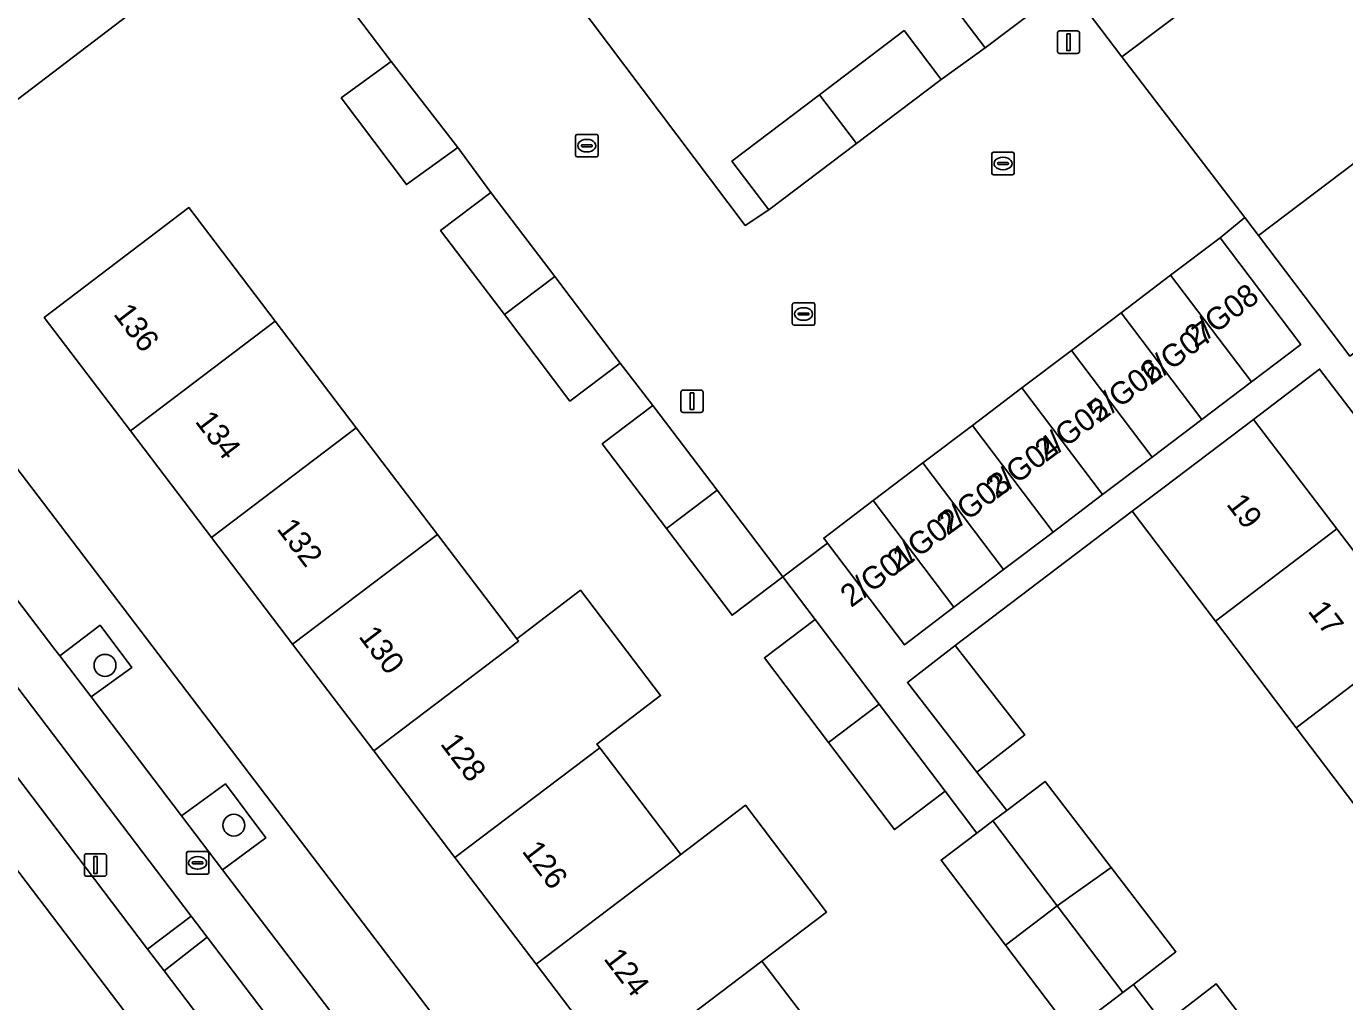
# Model space of a CAD drawing. Extents: x 160030 to 160839, y 385325 to 386450.
# Drawn here: x 160239.1 to 160297.9, y 385818.7 to 385862.2 of the extents above; entities that cross this region are included whole.
import ezdxf

# ---------------------------------------------------------------- set-up
doc = ezdxf.new("R2010")
doc.units = 0
for name, color, linetype in [('IMGEO_Berm_groen', 7, 'Continuous'), ('IMGEO_Boom', 7, 'Continuous'), ('IMGEO_Erf', 7, 'Continuous'), ('IMGEO_Fietspad_gesloten', 7, 'Continuous'), ('IMGEO_Groenvoorziening', 7, 'Continuous'), ('IMGEO_Kolk', 7, 'Continuous'), ('IMGEO_Lichtmast', 7, 'Continuous'), ('IMGEO_Muur', 7, 'Continuous'), ('IMGEO_Pand', 7, 'Continuous'), ('IMGEO_Pand_nummerreeks', 7, 'Continuous'), ('IMGEO_Parkeervlak_open', 7, 'Continuous'), ('IMGEO_Rijbaan_lokaal_gesloten', 7, 'Continuous'), ('IMGEO_Rijbaan_lokaal_open', 7, 'Continuous'), ('IMGEO_Rioolput', 7, 'Continuous'), ('IMGEO_Voetpad_open', 7, 'Continuous')]:
    doc.layers.add(name, color=color, linetype=linetype)

msp = doc.modelspace()

# ---------------------------------------------------------------- linework, layer by layer
at = {"layer": 'IMGEO_Berm_groen'}
msp.add_lwpolyline([(160233.389, 385835.707), (160244.52, 385821.036), (160246.466, 385822.505), (160230.756, 385843.173)], dxfattribs=at)
msp.add_lwpolyline([(160247.179, 385821.566), (160245.256, 385820.064), (160263.382, 385796.182), (160265.333, 385797.683)], close=True, dxfattribs=at)
at = {"layer": 'IMGEO_Boom'}
for centre in [(160242.62, 385833.683), (160248.364, 385826.556)]:
    msp.add_circle(centre, 0.489, dxfattribs=at)
at = {"layer": 'IMGEO_Erf'}
for points in [[(160301.566, 385871.532), (160297.525, 385868.388), (160293.797, 385865.487), (160292.351, 385867.345), (160290.31, 385865.8), (160291.853, 385863.763), (160287.96, 385860.815), (160293.444, 385853.652), (160294.063, 385852.843), (160298.997, 385856.578)], [(160282.773, 385821.214), (160279.908, 385824.999), (160281.504, 385826.208), (160280.082, 385828.07), (160277.823, 385826.36), (160274.88, 385830.247), (160272.027, 385834.013), (160274.287, 385835.724), (160272.844, 385837.629), (160270.584, 385835.918), (160267.655, 385839.784), (160264.796, 385843.558), (160267.057, 385845.271), (160265.599, 385847.156), (160263.356, 385845.459), (160260.431, 385849.321), (160257.588, 385853.075), (160259.832, 385854.773), (160258.354, 385856.767), (160256.06, 385855.12), (160253.159, 385858.988), (160255.38, 385860.608), (160250.09, 385867.593), (160231.698, 385853.575)], [(160263.526, 385863.454), (160271.171, 385853.296), (160272.221, 385853.995), (160270.574, 385856.169), (160274.482, 385859.128), (160278.257, 385861.986), (160279.903, 385859.811), (160281.865, 385861.216), (160280.157, 385863.471)], [(160265.465, 385815.599), (160261.846, 385820.356), (160258.227, 385825.114), (160254.608, 385829.871), (160250.989, 385834.629), (160247.371, 385839.385), (160243.752, 385844.143), (160239.913, 385849.19), (160246.36, 385854.094), (160250.206, 385849.038), (160253.824, 385844.281), (160257.443, 385839.524), (160260.981, 385834.873), (160263.823, 385837.034), (160267.396, 385832.337), (160264.554, 385830.176), (160264.68, 385830.01), (160268.299, 385825.253), (160271.19, 385827.447), (160274.802, 385822.686), (160271.917, 385820.496), (160275.536, 385815.739)], [(160231.475, 385851.922), (160294.583, 385769.052)], [(160302.585, 385841.09), (160301.695, 385840.441), (160299.39, 385843.472), (160296.787, 385846.896), (160293.838, 385844.652), (160297.555, 385839.767), (160301.163, 385835.026), (160304.771, 385830.284), (160308.379, 385825.543), (160311.987, 385820.801), (160315.595, 385816.06), (160319.203, 385811.318), (160322.811, 385806.577), (160326.419, 385801.836), (160330.134, 385796.954), (160325.136, 385793.154)], [(160306.531, 385816.65), (160302.935, 385821.4), (160299.338, 385826.151), (160295.742, 385830.901), (160292.145, 385835.651), (160288.43, 385840.558), (160280.539, 385834.575), (160283.637, 385830.585), (160281.5, 385828.925), (160282.831, 385827.212), (160284.541, 385828.507), (160287.487, 385824.671), (160290.373, 385820.913), (160288.481, 385819.459), (160289.842, 385817.685), (160292.178, 385819.479), (160295.203, 385815.538)], [(160285.703, 385817.345), (160282.773, 385821.214)]]:
    msp.add_lwpolyline(points, dxfattribs=at)
at = {"layer": 'IMGEO_Fietspad_gesloten'}
for points in [[(160255.179, 385814.968), (160253.742, 385816.855), (160253.509, 385817.161), (160247.864, 385824.573), (160246.034, 385826.977), (160241.998, 385832.275), (160240.606, 385834.102), (160240.383, 385834.395), (160233.264, 385843.741), (160231.245, 385846.393), (160228.63, 385849.846), (160226.256, 385852.983)], [(160225.501, 385850.09), (160229.487, 385844.842), (160230.756, 385843.173), (160246.466, 385822.505), (160247.179, 385821.566), (160265.333, 385797.683), (160266.08, 385796.701), (160277.414, 385781.789), (160278.156, 385780.813), (160284.988, 385771.823), (160286.475, 385769.866), (160289.911, 385765.345)]]:
    msp.add_lwpolyline(points, dxfattribs=at)
at = {"layer": 'IMGEO_Groenvoorziening'}
for points in [[(160242.401, 385835.469), (160240.606, 385834.102), (160241.998, 385832.275), (160243.811, 385833.588)], [(160247.987, 385828.396), (160246.034, 385826.977), (160247.864, 385824.573), (160249.79, 385825.991)]]:
    msp.add_lwpolyline(points, close=True, dxfattribs=at)
at = {"layer": 'IMGEO_Kolk'}
for p, q in [((160263.605, 385856.428), (160263.605, 385857.28)), ((160263.68, 385857.354), (160264.532, 385857.354)), ((160263.864, 385856.848), (160263.864, 385856.86)), ((160263.907, 385856.897), (160264.305, 385856.897)), ((160264.093, 385857.134), (160264.118, 385857.134)), ((160264.348, 385856.86), (160264.348, 385856.848)), ((160264.606, 385857.28), (160264.606, 385856.428)), ((160264.532, 385856.354), (160263.68, 385856.354)), ((160264.302, 385856.811), (160263.904, 385856.811)), ((160264.116, 385856.574), (160264.091, 385856.574)), ((160282.166, 385855.635), (160282.166, 385856.487)), ((160282.241, 385856.561), (160283.093, 385856.561)), ((160282.654, 385856.341), (160282.679, 385856.341)), ((160283.167, 385856.487), (160283.167, 385855.635)), ((160282.425, 385856.055), (160282.425, 385856.067)), ((160282.863, 385856.018), (160282.465, 385856.018)), ((160282.468, 385856.104), (160282.866, 385856.104)), ((160282.677, 385855.781), (160282.652, 385855.781)), ((160282.909, 385856.067), (160282.909, 385856.055)), ((160283.093, 385855.561), (160282.241, 385855.561)), ((160273.346, 385849.851), (160274.198, 385849.851)), ((160273.271, 385848.925), (160273.271, 385849.777)), ((160273.53, 385849.345), (160273.53, 385849.357)), ((160273.968, 385849.308), (160273.57, 385849.308)), ((160273.573, 385849.394), (160273.971, 385849.394)), ((160273.759, 385849.631), (160273.784, 385849.631)), ((160274.014, 385849.357), (160274.014, 385849.345)), ((160274.272, 385849.777), (160274.272, 385848.925)), ((160274.198, 385848.851), (160273.346, 385848.851)), ((160273.782, 385849.071), (160273.757, 385849.071))]:
    msp.add_line(p, q, dxfattribs=at)
for points in [[(160263.605, 385856.428), (160263.605, 385857.28)], [(160263.68, 385857.354), (160264.532, 385857.354)], [(160264.606, 385857.28), (160264.606, 385856.428)], [(160264.532, 385856.354), (160263.68, 385856.354)], [(160282.166, 385855.635), (160282.166, 385856.487)], [(160282.241, 385856.561), (160283.093, 385856.561)], [(160283.167, 385856.487), (160283.167, 385855.635)], [(160283.093, 385855.561), (160282.241, 385855.561)], [(160273.346, 385849.851), (160274.198, 385849.851)], [(160273.271, 385848.925), (160273.271, 385849.777)], [(160274.272, 385849.777), (160274.272, 385848.925)], [(160274.198, 385848.851), (160273.346, 385848.851)]]:
    msp.add_lwpolyline(points, dxfattribs=at)
for centre, radius, start, end in [((160263.682, 385857.278), 0.0765, 91.55205, 178.44795), ((160263.682, 385857.278), 0.0765, 91.55205, 178.44795), ((160263.904, 385856.857), 0.0403, 85.87752, 175.75265), ((160263.901, 385856.847), 0.0366, 178.93798, 274.71019), ((160264.305, 385856.854), 0.043, 264.86636, 352.45326), ((160264.309, 385856.859), 0.0386, 1.73085, 96.63898), ((160264.53, 385857.278), 0.0765, 1.55205, 88.44795), ((160264.53, 385857.278), 0.0765, 1.55205, 88.44795), ((160263.682, 385856.43), 0.0765, 181.55205, 268.44795), ((160263.682, 385856.43), 0.0765, 181.55205, 268.44795), ((160264.53, 385856.43), 0.0765, 271.55205, 358.44795), ((160264.53, 385856.43), 0.0765, 271.55205, 358.44795), ((160282.243, 385856.485), 0.0765, 91.55205, 178.44795), ((160282.243, 385856.485), 0.0765, 91.55205, 178.44795), ((160283.091, 385856.485), 0.0765, 1.55205, 88.44795), ((160283.091, 385856.485), 0.0765, 1.55205, 88.44795), ((160282.465, 385856.064), 0.0403, 85.87752, 175.75265), ((160282.462, 385856.054), 0.0366, 178.93798, 274.71019), ((160282.866, 385856.061), 0.043, 264.86636, 352.45326), ((160282.87, 385856.066), 0.0386, 1.73085, 96.63898), ((160282.243, 385855.637), 0.0765, 181.55205, 268.44795), ((160282.243, 385855.637), 0.0765, 181.55205, 268.44795), ((160283.091, 385855.637), 0.0765, 271.55205, 358.44795), ((160283.091, 385855.637), 0.0765, 271.55205, 358.44795), ((160273.348, 385849.775), 0.0765, 91.55205, 178.44795), ((160273.348, 385849.775), 0.0765, 91.55205, 178.44795), ((160274.196, 385849.775), 0.0765, 1.55205, 88.44795), ((160274.196, 385849.775), 0.0765, 1.55205, 88.44795), ((160273.57, 385849.354), 0.0403, 85.87752, 175.75265), ((160273.567, 385849.344), 0.0366, 178.93798, 274.71019), ((160273.971, 385849.351), 0.043, 264.86636, 352.45326), ((160273.975, 385849.356), 0.0386, 1.73085, 96.63898), ((160273.348, 385848.927), 0.0765, 181.55205, 268.44795), ((160273.348, 385848.927), 0.0765, 181.55205, 268.44795), ((160274.196, 385848.927), 0.0765, 271.55205, 358.44795), ((160274.196, 385848.927), 0.0765, 271.55205, 358.44795)]:
    msp.add_arc(centre, radius, start, end, dxfattribs=at)
for centre, major_axis, ratio, start_param, end_param in [((160264.092, 385856.854), (-0.387, 0.002), 0.722429, 4.712389, 7.853982), ((160264.117, 385856.854), (-0.39, 0.002), 0.717154, 1.570796, 4.712389), ((160282.653, 385856.061), (-0.387, 0.002), 0.722429, 4.712389, 7.853982), ((160282.678, 385856.061), (-0.39, 0.002), 0.717154, 1.570796, 4.712389), ((160273.758, 385849.351), (-0.387, 0.002), 0.722429, 4.712389, 7.853982), ((160273.783, 385849.351), (-0.39, 0.002), 0.717154, 1.570796, 4.712389)]:
    msp.add_ellipse(centre, major_axis=major_axis, ratio=ratio, start_param=start_param, end_param=end_param, dxfattribs=at)
at = {"layer": 'IMGEO_Lichtmast'}
for p, q in [((160285.09, 385861.069), (160285.09, 385861.869)), ((160285.09, 385861.869), (160285.09, 385861.069)), ((160285.19, 385861.969), (160285.98, 385861.969)), ((160285.98, 385861.969), (160285.19, 385861.969)), ((160286.08, 385861.869), (160286.08, 385861.069)), ((160286.08, 385861.069), (160286.08, 385861.869)), ((160285.98, 385860.969), (160285.19, 385860.969)), ((160285.19, 385860.969), (160285.98, 385860.969)), ((160268.302, 385845.06), (160268.302, 385845.86)), ((160268.302, 385845.86), (160268.302, 385845.06)), ((160268.402, 385845.96), (160269.192, 385845.96)), ((160269.192, 385845.96), (160268.402, 385845.96)), ((160269.292, 385845.86), (160269.292, 385845.06)), ((160269.292, 385845.06), (160269.292, 385845.86)), ((160269.192, 385844.96), (160268.402, 385844.96)), ((160268.402, 385844.96), (160269.192, 385844.96)), ((160241.699, 385824.381), (160241.699, 385825.181)), ((160241.699, 385825.181), (160241.699, 385824.381)), ((160241.799, 385825.281), (160242.589, 385825.281)), ((160242.589, 385825.281), (160241.799, 385825.281)), ((160242.689, 385825.181), (160242.689, 385824.381)), ((160242.689, 385824.381), (160242.689, 385825.181)), ((160242.589, 385824.281), (160241.799, 385824.281)), ((160241.799, 385824.281), (160242.589, 385824.281))]:
    msp.add_line(p, q, dxfattribs=at)
for points in [[(160285.51, 385861.844), (160285.66, 385861.844), (160285.66, 385861.094), (160285.51, 385861.094), (160285.51, 385861.844)], [(160268.722, 385845.835), (160268.872, 385845.835), (160268.872, 385845.085), (160268.722, 385845.085), (160268.722, 385845.835)], [(160242.119, 385825.156), (160242.269, 385825.156), (160242.269, 385824.406), (160242.119, 385824.406), (160242.119, 385825.156)]]:
    msp.add_lwpolyline(points, dxfattribs=at)
for centre, start, end in [((160285.19, 385861.869), 90, 180), ((160285.19, 385861.869), 90, 180), ((160285.98, 385861.869), 0, 90), ((160285.98, 385861.869), 360, 90), ((160285.19, 385861.069), 180, 270), ((160285.19, 385861.069), 180, 270), ((160285.98, 385861.069), 270, 0), ((160285.98, 385861.069), 270, 0), ((160268.402, 385845.86), 90, 180), ((160268.402, 385845.86), 90, 180), ((160269.192, 385845.86), 0, 90), ((160269.192, 385845.86), 360, 90), ((160268.402, 385845.06), 180, 270), ((160268.402, 385845.06), 180, 270), ((160269.192, 385845.06), 270, 0), ((160269.192, 385845.06), 270, 0), ((160241.799, 385825.181), 90, 180), ((160241.799, 385825.181), 90, 180), ((160242.589, 385825.181), 0, 90), ((160242.589, 385825.181), 360, 90), ((160241.799, 385824.381), 180, 270), ((160241.799, 385824.381), 180, 270), ((160242.589, 385824.381), 270, 0), ((160242.589, 385824.381), 270, 0)]:
    msp.add_arc(centre, 0.1, start, end, dxfattribs=at)
at = {"layer": 'IMGEO_Muur'}
for points in [[(160263.526, 385863.454), (160271.171, 385853.296)], [(160287.96, 385860.815), (160293.444, 385853.652)], [(160293.444, 385853.652), (160294.063, 385852.843)]]:
    msp.add_lwpolyline(points, dxfattribs=at)
at = {"layer": 'IMGEO_Pand'}
for points in [[(160285.544, 385864.002), (160285.742, 385864.152), (160284.035, 385866.407), (160280.157, 385863.471), (160281.865, 385861.216)], [(160291.853, 385863.763), (160290.31, 385865.8), (160286.417, 385862.852), (160287.96, 385860.815)], [(160279.903, 385859.811), (160278.257, 385861.986), (160274.482, 385859.128), (160276.129, 385856.954)], [(160255.38, 385860.608), (160253.159, 385858.988), (160256.06, 385855.12), (160258.354, 385856.767)], [(160276.129, 385856.954), (160274.482, 385859.128), (160270.574, 385856.169), (160272.221, 385853.995)], [(160294.063, 385852.843), (160298.129, 385847.473), (160303.062, 385851.208), (160298.997, 385856.578)], [(160259.832, 385854.773), (160257.588, 385853.075), (160260.431, 385849.321), (160262.673, 385851.02)], [(160250.206, 385849.038), (160246.36, 385854.094), (160239.913, 385849.19), (160243.752, 385844.143)], [(160295.951, 385847.992), (160292.35, 385852.748), (160290.14, 385851.075), (160293.741, 385846.319)], [(160262.673, 385851.02), (160260.431, 385849.321), (160263.356, 385845.459), (160265.599, 385847.156)], [(160293.741, 385846.319), (160290.14, 385851.075), (160287.93, 385849.401), (160291.531, 385844.645)], [(160291.531, 385844.645), (160287.93, 385849.401), (160285.72, 385847.728), (160289.321, 385842.972)], [(160243.752, 385844.143), (160247.371, 385839.385), (160253.824, 385844.281), (160250.206, 385849.038)], [(160289.321, 385842.972), (160285.72, 385847.728), (160283.51, 385846.055), (160287.11, 385841.299)], [(160287.11, 385841.299), (160283.51, 385846.055), (160281.299, 385844.381), (160284.9, 385839.625)], [(160267.057, 385845.271), (160264.796, 385843.558), (160267.655, 385839.784), (160269.916, 385841.496)], [(160297.555, 385839.767), (160293.838, 385844.652), (160289.852, 385841.635), (160288.43, 385840.558), (160292.145, 385835.651)], [(160257.443, 385839.524), (160253.824, 385844.281), (160247.371, 385839.385), (160250.989, 385834.629)], [(160284.9, 385839.625), (160281.299, 385844.381), (160279.089, 385842.708), (160282.69, 385837.952)], [(160282.69, 385837.952), (160279.089, 385842.708), (160276.879, 385841.034), (160280.48, 385836.278)], [(160269.916, 385841.496), (160267.655, 385839.784), (160270.584, 385835.918), (160272.844, 385837.629)], [(160278.27, 385834.605), (160280.48, 385836.278), (160276.879, 385841.034), (160274.669, 385839.361), (160274.843, 385839.132)], [(160261.061, 385834.768), (160260.981, 385834.873), (160257.443, 385839.524), (160250.989, 385834.629), (160254.608, 385829.871)], [(160292.145, 385835.651), (160295.742, 385830.901), (160301.163, 385835.026), (160297.555, 385839.767)], [(160264.68, 385830.01), (160264.554, 385830.176), (160267.396, 385832.337), (160263.823, 385837.034), (160260.981, 385834.873), (160261.061, 385834.768), (160254.608, 385829.871), (160258.227, 385825.114)], [(160274.287, 385835.724), (160272.027, 385834.013), (160274.88, 385830.247), (160277.139, 385831.957)], [(160278.402, 385832.916), (160281.5, 385828.925), (160283.637, 385830.585), (160280.539, 385834.575)], [(160304.771, 385830.284), (160301.163, 385835.026), (160295.742, 385830.901), (160299.338, 385826.151)], [(160277.139, 385831.957), (160274.88, 385830.247), (160277.823, 385826.36), (160280.082, 385828.07)], [(160268.299, 385825.253), (160264.68, 385830.01), (160258.227, 385825.114), (160261.846, 385820.356)], [(160282.831, 385827.212), (160282.218, 385826.748), (160285.083, 385822.963), (160287.487, 385824.671), (160284.541, 385828.507)], [(160271.917, 385820.496), (160274.802, 385822.686), (160271.19, 385827.447), (160268.299, 385825.253), (160261.846, 385820.356), (160265.465, 385815.599)], [(160282.218, 385826.748), (160281.504, 385826.208), (160279.908, 385824.999), (160282.773, 385821.214), (160285.083, 385822.963)], [(160287.487, 385824.671), (160285.083, 385822.963), (160288.011, 385819.098), (160288.481, 385819.459), (160290.373, 385820.913)], [(160285.083, 385822.963), (160282.773, 385821.214), (160285.703, 385817.345), (160287.329, 385818.58), (160288.011, 385819.098)], [(160275.536, 385815.739), (160271.917, 385820.496), (160265.465, 385815.599), (160269.083, 385810.842)], [(160295.203, 385815.538), (160292.178, 385819.479), (160289.842, 385817.685), (160292.859, 385813.755)]]:
    msp.add_lwpolyline(points, close=True, dxfattribs=at)
at = {"layer": 'IMGEO_Parkeervlak_open'}
for points in [[(160228.526, 385837.944), (160279.223, 385771.231)], [(160278.331, 385776.525), (160276.196, 385779.33), (160275.455, 385780.303), (160264.086, 385795.256), (160263.382, 385796.182), (160245.256, 385820.064), (160244.52, 385821.036), (160233.389, 385835.707)]]:
    msp.add_lwpolyline(points, dxfattribs=at)
at = {"layer": 'IMGEO_Rijbaan_lokaal_gesloten'}
msp.add_lwpolyline([(160278.119, 385766.625), (160281.119, 385768.748), (160279.223, 385771.231), (160228.526, 385837.944), (160226.826, 385840.11), (160225.579, 385841.807), (160224.418, 385843.405), (160212.483, 385859.092), (160208.116, 385864.799), (160181.103, 385900.416), (160180.357, 385901.406), (160179.584, 385902.465), (160175.453, 385899.617), (160202.503, 385863.561), (160272.577, 385773.993)], close=True, dxfattribs=at)
at = {"layer": 'IMGEO_Rijbaan_lokaal_open'}
for points in [[(160250.09, 385867.593), (160255.38, 385860.608), (160258.354, 385856.767), (160259.832, 385854.773), (160262.673, 385851.02), (160265.599, 385847.156), (160267.057, 385845.271), (160269.916, 385841.496), (160272.844, 385837.629), (160274.843, 385839.132), (160274.669, 385839.361), (160276.879, 385841.034), (160279.089, 385842.708), (160281.299, 385844.381), (160283.51, 385846.055), (160285.72, 385847.728), (160287.93, 385849.401), (160290.14, 385851.075), (160292.35, 385852.748), (160293.444, 385853.652), (160287.96, 385860.815), (160286.417, 385862.852)], [(160285.544, 385864.002), (160281.865, 385861.216), (160279.903, 385859.811), (160276.129, 385856.954), (160272.221, 385853.995), (160271.171, 385853.296), (160263.526, 385863.454)]]:
    msp.add_lwpolyline(points, dxfattribs=at)
at = {"layer": 'IMGEO_Rioolput'}
for p, q in [((160246.251, 385824.452), (160246.251, 385825.304)), ((160246.326, 385825.378), (160247.178, 385825.378)), ((160246.739, 385825.158), (160246.764, 385825.158)), ((160247.252, 385825.304), (160247.252, 385824.452)), ((160246.51, 385824.872), (160246.51, 385824.884)), ((160246.948, 385824.835), (160246.55, 385824.835)), ((160246.553, 385824.921), (160246.951, 385824.921)), ((160246.762, 385824.598), (160246.737, 385824.598)), ((160246.994, 385824.884), (160246.994, 385824.872)), ((160247.178, 385824.378), (160246.326, 385824.378))]:
    msp.add_line(p, q, dxfattribs=at)
for points in [[(160246.251, 385824.452), (160246.251, 385825.304)], [(160246.326, 385825.378), (160247.178, 385825.378)], [(160247.252, 385825.304), (160247.252, 385824.452)], [(160247.178, 385824.378), (160246.326, 385824.378)]]:
    msp.add_lwpolyline(points, dxfattribs=at)
for centre, radius, start, end in [((160246.328, 385825.302), 0.0765, 91.55205, 178.44795), ((160246.328, 385825.302), 0.0765, 91.55205, 178.44795), ((160247.176, 385825.302), 0.0765, 1.55205, 88.44795), ((160247.176, 385825.302), 0.0765, 1.55205, 88.44795), ((160246.55, 385824.881), 0.0403, 85.87752, 175.75265), ((160246.547, 385824.871), 0.0366, 178.93798, 274.71019), ((160246.951, 385824.878), 0.043, 264.86636, 352.45326), ((160246.955, 385824.883), 0.0386, 1.73085, 96.63898), ((160246.328, 385824.454), 0.0765, 181.55205, 268.44795), ((160246.328, 385824.454), 0.0765, 181.55205, 268.44795), ((160247.176, 385824.454), 0.0765, 271.55205, 358.44795), ((160247.176, 385824.454), 0.0765, 271.55205, 358.44795)]:
    msp.add_arc(centre, radius, start, end, dxfattribs=at)
for centre, major_axis, ratio, start_param, end_param in [((160246.738, 385824.878), (-0.387, 0.002), 0.722429, 4.712389, 7.853982), ((160246.763, 385824.878), (-0.39, 0.002), 0.717154, 1.570796, 4.712389)]:
    msp.add_ellipse(centre, major_axis=major_axis, ratio=ratio, start_param=start_param, end_param=end_param, dxfattribs=at)
at = {"layer": 'IMGEO_Voetpad_open'}
for points in [[(160250.09, 385867.593), (160251.271, 385868.357), (160248.486, 385870.73), (160229.444, 385856.309), (160231.698, 385853.575)], [(160244.52, 385821.036), (160245.256, 385820.064), (160247.179, 385821.566), (160246.466, 385822.505)]]:
    msp.add_lwpolyline(points, close=True, dxfattribs=at)
for points in [[(160298.129, 385847.473), (160294.063, 385852.843), (160293.444, 385853.652), (160292.35, 385852.748), (160295.951, 385847.992), (160293.741, 385846.319), (160291.531, 385844.645), (160289.321, 385842.972), (160287.11, 385841.299), (160284.9, 385839.625), (160282.69, 385837.952), (160280.48, 385836.278), (160278.27, 385834.605), (160274.843, 385839.132), (160272.844, 385837.629), (160274.287, 385835.724), (160277.139, 385831.957), (160280.082, 385828.07), (160281.504, 385826.208), (160282.218, 385826.748), (160282.831, 385827.212), (160281.5, 385828.925), (160278.402, 385832.916), (160280.539, 385834.575), (160288.43, 385840.558), (160289.852, 385841.635), (160293.838, 385844.652), (160296.787, 385846.896), (160299.39, 385843.472)], [(160296.233, 385766.885), (160294.598, 385769.03), (160294.583, 385769.052), (160231.475, 385851.922)], [(160228.63, 385849.846), (160231.245, 385846.393), (160233.413, 385848.023), (160235.425, 385845.37), (160233.264, 385843.741), (160240.383, 385834.395), (160240.606, 385834.102), (160242.401, 385835.469), (160243.811, 385833.588), (160241.998, 385832.275), (160246.034, 385826.977), (160247.987, 385828.396), (160249.79, 385825.991), (160247.864, 385824.573), (160253.509, 385817.161)], [(160289.842, 385817.685), (160288.481, 385819.459), (160288.011, 385819.098), (160287.329, 385818.58)]]:
    msp.add_lwpolyline(points, dxfattribs=at)

# ---------------------------------------------------------------- texts
at = {"layer": 'IMGEO_Pand_nummerreeks'}
for s, rotation, p in [('2/G08', 36.76958, (160291.243, 385847.796)), ('136', 307.25911, (160242.961, 385849.344)), ('2/G07', 36.76958, (160289.264, 385846.146)), ('2/G06', 36.76958, (160286.958, 385844.469)), ('2/G05', 36.76958, (160284.573, 385842.72)), ('134', 307.25911, (160246.605, 385844.554)), ('2/G04', 36.76958, (160282.381, 385841.082)), ('2/G03', 36.76958, (160280.189, 385839.444)), ('19', 307.26947, (160292.597, 385840.866)), ('2/G02', 36.76958, (160277.992, 385837.802)), ('132', 307.25911, (160250.248, 385839.765)), ('2/G01', 36.76958, (160275.893, 385836.233)), ('17', 307.26947, (160296.227, 385836.096)), ('130', 307.25923, (160253.897, 385834.969)), ('128', 307.25923, (160257.541, 385830.179)), ('126', 307.25911, (160261.182, 385825.391)), ('124', 307.25923, (160264.826, 385820.6))]:
    msp.add_text(s, height=1, rotation=rotation, dxfattribs=at).set_placement(p)

doc.saveas('drawing.dxf')
